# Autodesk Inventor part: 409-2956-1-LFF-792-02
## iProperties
Shininess: 64.0
Angle Display Precision: 2
Document Length Units: 11272
Document Angle Units: 11279
Document Time Units: 11290
Document Mass Units: 11286
Document Length Units Precision: 3
Document Angle Units Precision: 2
Compacted: True
Created: 2002-04
Part Number: 409-2956-1-LFF-792-02
Description: 2" PIPE MOUNT ANGLE
Document SubType Name: Modeling
Designer: S. Boerckel
Mass: 1123.41 g
Surface Area: 473.124 cm^2
Volume: 139.902 cm^3
Density: 8.03 g/cm^3
Cost Center: 3 x 3 x 1/4 ANGLE
Material: STAINLESS STEEL, 304
Engineer: S. Boerckel
Density: 0.0
Volumn: 0.0
Area: 0.0
PropertySet Name: Model Information
Control State: 0
Master: False
Checked Out: False
length: 6.000 in
SMR: =<COST CENTER> - <MATERIAL>
Author: S. Boerckel
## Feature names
1. Extrusion1
2. Hole1
